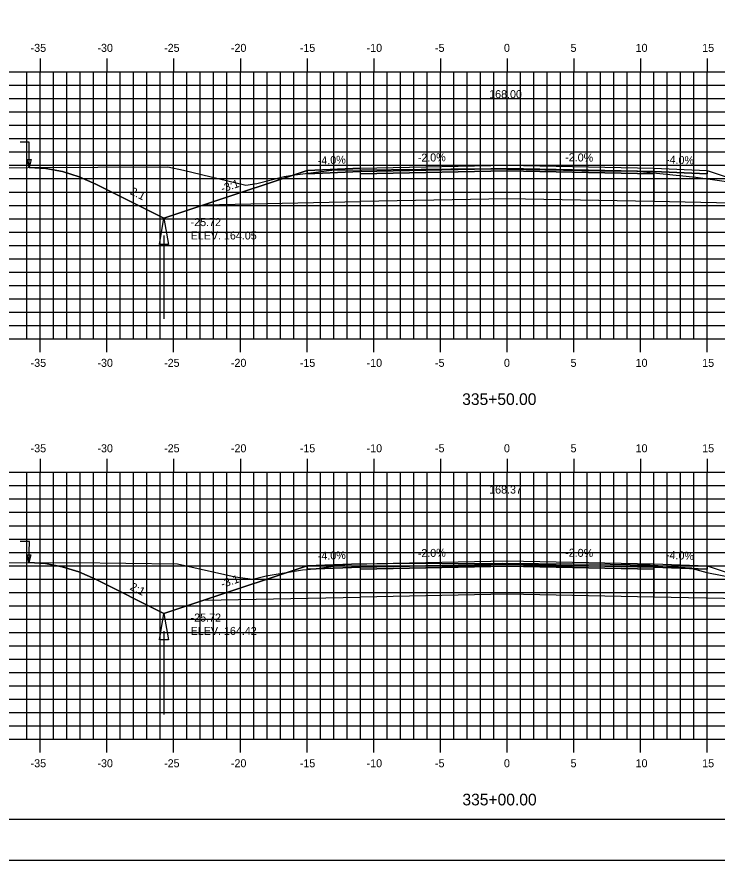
# Model space of a CAD drawing. Extents: x 1142089 to 1142259, y 608981 to 609091.
# Drawn here: x 1142135.8 to 1142188.3, y 608981.3 to 609044.5 of the extents above; entities that cross this region are included whole.
import ezdxf

# ---------------------------------------------------------------- set-up
doc = ezdxf.new("R2010")
doc.units = 0
for name, color, linetype in [('ANNOTATION', 7, 'Continuous'), ('BORDER', 7, 'Continuous'), ('D_Drainage_Ditch_Line', 7, 'Continuous'), ('D_Roadway_Centerline', 7, 'Continuous'), ('D_Roadway_Centerline_Text', 7, 'Continuous'), ('D_Roadway_Edge_Shoulder', 7, 'Continuous'), ('D_Roadway_Edge_TW', 7, 'Continuous'), ('D_Roadway_Pavement', 7, 'Continuous'), ('D_Roadway_SlopeLines', 7, 'Continuous'), ('D_Roadway_SubGrade', 7, 'Continuous'), ('D_Text_Standard', 7, 'Continuous'), ('H_V ANNOTATION', 7, 'Continuous'), ('MAJOR', 7, 'Continuous'), ('MINOR', 7, 'Continuous'), ('PLOT BOUNDARY', 7, 'Continuous'), ('S_Roadway_Centerline', 7, 'Continuous')]:
    doc.layers.add(name, color=color, linetype=linetype)

msp = doc.modelspace()

# ---------------------------------------------------------------- linework, layer by layer
for points in [[(1142136.708, 609033.172), (1142137.958, 609033.099), (1142139.208, 609032.868), (1142140.458, 609032.48), (1142141.708, 609031.934), (1142146.816, 609029.38), (1142149.816, 609030.38), (1142157.539, 609032.955), (1142157.54, 609032.955), (1142161.54, 609033.115), (1142172.54, 609033.335), (1142183.54, 609033.115), (1142187.54, 609032.955), (1142195.264, 609030.38), (1142198.264, 609029.38), (1142201.423, 609030.96), (1142202.673, 609031.506), (1142203.923, 609031.896), (1142205.173, 609032.129), (1142206.423, 609032.206)], [(1142136.678, 609003.566), (1142137.928, 609003.49), (1142139.178, 609003.257), (1142140.428, 609002.867), (1142141.678, 609002.32), (1142146.816, 608999.752), (1142149.816, 609000.752), (1142157.539, 609003.326), (1142157.54, 609003.326), (1142161.54, 609003.486), (1142172.54, 609003.706), (1142183.54, 609003.486), (1142187.54, 609003.326), (1142195.264, 609000.752), (1142198.264, 608999.752), (1142201.207, 609001.223), (1142202.457, 609001.767), (1142203.707, 609002.15), (1142204.957, 609002.371), (1142206.207, 609002.43)]]:
    msp.add_lwpolyline(points)
at = {"layer": 'BORDER'}
msp.add_lwpolyline([(1142097.541, 608984.335), (1142257.541, 608984.335), (1142257.541, 609089.335), (1142097.541, 609089.335)], close=True, dxfattribs=at)
at = {"layer": 'D_Drainage_Ditch_Line'}
for p, q in [((1142146.816, 609028.068), (1142146.815, 609021.824)), ((1142146.816, 608998.439), (1142146.815, 608992.196))]:
    msp.add_line(p, q, dxfattribs=at)
for points in [[(1142147.144, 609027.412), (1142146.488, 609027.412), (1142146.816, 609029.38)], [(1142147.144, 608997.783), (1142146.488, 608997.783), (1142146.816, 608999.752)]]:
    msp.add_lwpolyline(points, close=True, dxfattribs=at)
at = {"layer": 'D_Roadway_Edge_Shoulder'}
for points in [[(1142161.54, 609033.115), (1142157.54, 609032.955), (1142157.54, 609032.705), (1142161.54, 609032.865)], [(1142183.54, 609033.115), (1142187.54, 609032.955), (1142187.54, 609032.705), (1142183.54, 609032.865)], [(1142161.54, 609003.486), (1142157.54, 609003.326), (1142157.54, 609003.076), (1142161.54, 609003.236)], [(1142183.54, 609003.486), (1142187.54, 609003.326), (1142187.54, 609003.076), (1142183.54, 609003.236)]]:
    msp.add_lwpolyline(points, close=True, dxfattribs=at)
at = {"layer": 'D_Roadway_Edge_TW'}
for points in [[(1142161.54, 609032.865), (1142161.54, 609033.115), (1142172.54, 609033.335), (1142183.54, 609033.115), (1142183.54, 609032.865), (1142172.54, 609033.085)], [(1142161.54, 609003.236), (1142161.54, 609003.486), (1142172.54, 609003.706), (1142183.54, 609003.486), (1142183.54, 609003.236), (1142172.54, 609003.456)]]:
    msp.add_lwpolyline(points, close=True, dxfattribs=at)
at = {"layer": 'D_Roadway_Pavement'}
for points in [[(1142161.54, 609032.698), (1142161.54, 609032.865), (1142172.54, 609033.085), (1142183.54, 609032.865), (1142183.54, 609032.698), (1142172.54, 609032.918)], [(1142161.54, 609003.069), (1142161.54, 609003.236), (1142172.54, 609003.456), (1142183.54, 609003.236), (1142183.54, 609003.069), (1142172.54, 609003.289)]]:
    msp.add_lwpolyline(points, close=True, dxfattribs=at)
at = {"layer": 'D_Roadway_SlopeLines'}
for points in [[(1142146.816, 609029.38), (1142141.708, 609031.934), (1142140.458, 609032.48), (1142139.208, 609032.868), (1142137.958, 609033.099), (1142136.708, 609033.172)], [(1142149.816, 609030.38), (1142146.816, 609029.38)], [(1142146.816, 608999.752), (1142141.678, 609002.32), (1142140.428, 609002.867), (1142139.178, 609003.257), (1142137.928, 609003.49), (1142136.678, 609003.566)], [(1142149.816, 609000.752), (1142146.816, 608999.752)]]:
    msp.add_lwpolyline(points, dxfattribs=at)
at = {"layer": 'D_Roadway_SubGrade'}
for points in [[(1142161.54, 609032.698), (1142161.54, 609032.865), (1142157.54, 609032.705), (1142157.54, 609032.955), (1142157.539, 609032.955), (1142149.816, 609030.38), (1142161.54, 609030.615)], [(1142161.54, 609030.615), (1142161.54, 609032.698), (1142172.54, 609032.918), (1142183.54, 609032.698), (1142183.54, 609030.615), (1142172.54, 609030.835)], [(1142183.54, 609032.698), (1142183.54, 609032.865), (1142187.54, 609032.705), (1142187.54, 609032.955), (1142187.54, 609032.955), (1142195.264, 609030.38), (1142183.54, 609030.615)], [(1142161.54, 609003.069), (1142161.54, 609003.236), (1142157.54, 609003.076), (1142157.54, 609003.326), (1142157.539, 609003.326), (1142149.816, 609000.752), (1142161.54, 609000.986)], [(1142161.54, 609000.986), (1142161.54, 609003.069), (1142172.54, 609003.289), (1142183.54, 609003.069), (1142183.54, 609000.986), (1142172.54, 609001.206)], [(1142183.54, 609003.069), (1142183.54, 609003.236), (1142187.54, 609003.076), (1142187.54, 609003.326), (1142187.54, 609003.326), (1142195.264, 609000.752), (1142183.54, 609000.986)]]:
    msp.add_lwpolyline(points, close=True, dxfattribs=at)
at = {"layer": 'D_Text_Standard'}
for points in [[(1142136.708, 609033.184), (1142136.718, 609035.076), (1142136.038, 609035.076)], [(1142136.678, 609003.57), (1142136.725, 609005.14), (1142136.045, 609005.14)]]:
    msp.add_lwpolyline(points, dxfattribs=at)
for points in [[(1142136.708, 609033.184), (1142136.566, 609033.767), (1142136.857, 609033.765)], [(1142136.678, 609003.57), (1142136.55, 609004.157), (1142136.841, 609004.148)]]:
    msp.add_lwpolyline(points, close=True, dxfattribs=at)
at = {"layer": 'MAJOR'}
for p, q in [((1142137.54, 609041.337), (1142137.54, 609040.335)), ((1142142.54, 609041.337), (1142142.54, 609040.335)), ((1142147.54, 609041.337), (1142147.54, 609040.335)), ((1142152.54, 609041.337), (1142152.54, 609040.335)), ((1142157.54, 609041.337), (1142157.54, 609040.335)), ((1142162.54, 609041.337), (1142162.54, 609040.335)), ((1142167.54, 609041.337), (1142167.54, 609040.335)), ((1142172.54, 609041.337), (1142172.54, 609040.335)), ((1142177.54, 609041.337), (1142177.54, 609040.335)), ((1142182.54, 609041.337), (1142182.54, 609040.335)), ((1142187.54, 609041.337), (1142187.54, 609040.335)), ((1142102.54, 609040.335), (1142242.54, 609040.335)), ((1142102.54, 609040.335), (1142242.54, 609040.335)), ((1142137.54, 609020.335), (1142137.54, 609040.335)), ((1142142.54, 609020.335), (1142142.54, 609040.335)), ((1142147.54, 609020.335), (1142147.54, 609040.335)), ((1142152.54, 609020.335), (1142152.54, 609040.335)), ((1142157.54, 609020.335), (1142157.54, 609040.335)), ((1142162.54, 609020.335), (1142162.54, 609040.335)), ((1142167.54, 609020.335), (1142167.54, 609040.335)), ((1142172.54, 609020.335), (1142172.54, 609040.335)), ((1142177.54, 609020.335), (1142177.54, 609040.335)), ((1142182.54, 609020.335), (1142182.54, 609040.335)), ((1142187.54, 609020.335), (1142187.54, 609040.335)), ((1142102.54, 609035.335), (1142242.54, 609035.335)), ((1142102.54, 609030.335), (1142242.54, 609030.335)), ((1142102.54, 609025.335), (1142242.54, 609025.335)), ((1142102.54, 609020.335), (1142242.54, 609020.335)), ((1142102.54, 609020.335), (1142242.54, 609020.335)), ((1142137.54, 609019.333), (1142137.54, 609020.335)), ((1142142.54, 609019.333), (1142142.54, 609020.335)), ((1142147.54, 609019.333), (1142147.54, 609020.335)), ((1142152.54, 609019.333), (1142152.54, 609020.335)), ((1142157.54, 609019.333), (1142157.54, 609020.335)), ((1142162.54, 609019.333), (1142162.54, 609020.335)), ((1142167.54, 609019.333), (1142167.54, 609020.335)), ((1142172.54, 609019.333), (1142172.54, 609020.335)), ((1142177.54, 609019.333), (1142177.54, 609020.335)), ((1142182.54, 609019.333), (1142182.54, 609020.335)), ((1142187.54, 609019.333), (1142187.54, 609020.335)), ((1142137.54, 609011.337), (1142137.54, 609010.335)), ((1142142.54, 609011.337), (1142142.54, 609010.335)), ((1142147.54, 609011.337), (1142147.54, 609010.335)), ((1142152.54, 609011.337), (1142152.54, 609010.335)), ((1142157.54, 609011.337), (1142157.54, 609010.335)), ((1142162.54, 609011.337), (1142162.54, 609010.335)), ((1142167.54, 609011.337), (1142167.54, 609010.335)), ((1142172.54, 609011.337), (1142172.54, 609010.335)), ((1142177.54, 609011.337), (1142177.54, 609010.335)), ((1142182.54, 609011.337), (1142182.54, 609010.335)), ((1142187.54, 609011.337), (1142187.54, 609010.335)), ((1142102.54, 609010.335), (1142242.54, 609010.335)), ((1142102.54, 609010.335), (1142242.54, 609010.335)), ((1142137.54, 608990.335), (1142137.54, 609010.335)), ((1142142.54, 608990.335), (1142142.54, 609010.335)), ((1142147.54, 608990.335), (1142147.54, 609010.335)), ((1142152.54, 608990.335), (1142152.54, 609010.335)), ((1142157.54, 608990.335), (1142157.54, 609010.335)), ((1142162.54, 608990.335), (1142162.54, 609010.335)), ((1142167.54, 608990.335), (1142167.54, 609010.335)), ((1142172.54, 608990.335), (1142172.54, 609010.335)), ((1142177.54, 608990.335), (1142177.54, 609010.335)), ((1142182.54, 608990.335), (1142182.54, 609010.335)), ((1142187.54, 608990.335), (1142187.54, 609010.335)), ((1142102.54, 609005.335), (1142242.54, 609005.335)), ((1142102.54, 609000.335), (1142242.54, 609000.335)), ((1142102.54, 608995.335), (1142242.54, 608995.335)), ((1142102.54, 608990.335), (1142242.54, 608990.335)), ((1142102.54, 608990.335), (1142242.54, 608990.335)), ((1142137.54, 608989.333), (1142137.54, 608990.335)), ((1142142.54, 608989.333), (1142142.54, 608990.335)), ((1142147.54, 608989.333), (1142147.54, 608990.335)), ((1142152.54, 608989.333), (1142152.54, 608990.335)), ((1142157.54, 608989.333), (1142157.54, 608990.335)), ((1142162.54, 608989.333), (1142162.54, 608990.335)), ((1142167.54, 608989.333), (1142167.54, 608990.335)), ((1142172.54, 608989.333), (1142172.54, 608990.335)), ((1142177.54, 608989.333), (1142177.54, 608990.335)), ((1142182.54, 608989.333), (1142182.54, 608990.335)), ((1142187.54, 608989.333), (1142187.54, 608990.335))]:
    msp.add_line(p, q, dxfattribs=at)
at = {"layer": 'MINOR'}
for p, q in [((1142136.54, 609020.335), (1142136.54, 609040.335)), ((1142138.54, 609020.335), (1142138.54, 609040.335)), ((1142139.54, 609020.335), (1142139.54, 609040.335)), ((1142140.54, 609020.335), (1142140.54, 609040.335)), ((1142141.54, 609020.335), (1142141.54, 609040.335)), ((1142143.54, 609020.335), (1142143.54, 609040.335)), ((1142144.54, 609020.335), (1142144.54, 609040.335)), ((1142145.54, 609020.335), (1142145.54, 609040.335)), ((1142146.54, 609020.335), (1142146.54, 609040.335)), ((1142148.54, 609020.335), (1142148.54, 609040.335)), ((1142149.54, 609020.335), (1142149.54, 609040.335)), ((1142150.54, 609020.335), (1142150.54, 609040.335)), ((1142151.54, 609020.335), (1142151.54, 609040.335)), ((1142153.54, 609020.335), (1142153.54, 609040.335)), ((1142154.54, 609020.335), (1142154.54, 609040.335)), ((1142155.54, 609020.335), (1142155.54, 609040.335)), ((1142156.54, 609020.335), (1142156.54, 609040.335)), ((1142158.54, 609020.335), (1142158.54, 609040.335)), ((1142159.54, 609020.335), (1142159.54, 609040.335)), ((1142160.54, 609020.335), (1142160.54, 609040.335)), ((1142161.54, 609020.335), (1142161.54, 609040.335)), ((1142163.54, 609020.335), (1142163.54, 609040.335)), ((1142164.54, 609020.335), (1142164.54, 609040.335)), ((1142165.54, 609020.335), (1142165.54, 609040.335)), ((1142166.54, 609020.335), (1142166.54, 609040.335)), ((1142168.54, 609020.335), (1142168.54, 609040.335)), ((1142169.54, 609020.335), (1142169.54, 609040.335)), ((1142170.54, 609020.335), (1142170.54, 609040.335)), ((1142171.54, 609020.335), (1142171.54, 609040.335)), ((1142173.54, 609020.335), (1142173.54, 609040.335)), ((1142174.54, 609020.335), (1142174.54, 609040.335)), ((1142175.54, 609020.335), (1142175.54, 609040.335)), ((1142176.54, 609020.335), (1142176.54, 609040.335)), ((1142178.54, 609020.335), (1142178.54, 609040.335)), ((1142179.54, 609020.335), (1142179.54, 609040.335)), ((1142180.54, 609020.335), (1142180.54, 609040.335)), ((1142181.54, 609020.335), (1142181.54, 609040.335)), ((1142183.54, 609020.335), (1142183.54, 609040.335)), ((1142184.54, 609020.335), (1142184.54, 609040.335)), ((1142185.54, 609020.335), (1142185.54, 609040.335)), ((1142186.54, 609020.335), (1142186.54, 609040.335)), ((1142102.54, 609039.335), (1142242.54, 609039.335)), ((1142102.54, 609038.335), (1142242.54, 609038.335)), ((1142102.54, 609037.335), (1142242.54, 609037.335)), ((1142102.54, 609036.335), (1142242.54, 609036.335)), ((1142102.54, 609034.335), (1142242.54, 609034.335)), ((1142102.54, 609033.335), (1142242.54, 609033.335)), ((1142102.54, 609032.335), (1142242.54, 609032.335)), ((1142102.54, 609031.335), (1142242.54, 609031.335)), ((1142102.54, 609029.335), (1142242.54, 609029.335)), ((1142102.54, 609028.335), (1142242.54, 609028.335)), ((1142102.54, 609027.335), (1142242.54, 609027.335)), ((1142102.54, 609026.335), (1142242.54, 609026.335)), ((1142102.54, 609024.335), (1142242.54, 609024.335)), ((1142102.54, 609023.335), (1142242.54, 609023.335)), ((1142102.54, 609022.335), (1142242.54, 609022.335)), ((1142102.54, 609021.335), (1142242.54, 609021.335)), ((1142136.54, 608990.335), (1142136.54, 609010.335)), ((1142138.54, 608990.335), (1142138.54, 609010.335)), ((1142139.54, 608990.335), (1142139.54, 609010.335)), ((1142140.54, 608990.335), (1142140.54, 609010.335)), ((1142141.54, 608990.335), (1142141.54, 609010.335)), ((1142143.54, 608990.335), (1142143.54, 609010.335)), ((1142144.54, 608990.335), (1142144.54, 609010.335)), ((1142145.54, 608990.335), (1142145.54, 609010.335)), ((1142146.54, 608990.335), (1142146.54, 609010.335)), ((1142148.54, 608990.335), (1142148.54, 609010.335)), ((1142149.54, 608990.335), (1142149.54, 609010.335)), ((1142150.54, 608990.335), (1142150.54, 609010.335)), ((1142151.54, 608990.335), (1142151.54, 609010.335)), ((1142153.54, 608990.335), (1142153.54, 609010.335)), ((1142154.54, 608990.335), (1142154.54, 609010.335)), ((1142155.54, 608990.335), (1142155.54, 609010.335)), ((1142156.54, 608990.335), (1142156.54, 609010.335)), ((1142158.54, 608990.335), (1142158.54, 609010.335)), ((1142159.54, 608990.335), (1142159.54, 609010.335)), ((1142160.54, 608990.335), (1142160.54, 609010.335)), ((1142161.54, 608990.335), (1142161.54, 609010.335)), ((1142163.54, 608990.335), (1142163.54, 609010.335)), ((1142164.54, 608990.335), (1142164.54, 609010.335)), ((1142165.54, 608990.335), (1142165.54, 609010.335)), ((1142166.54, 608990.335), (1142166.54, 609010.335)), ((1142168.54, 608990.335), (1142168.54, 609010.335)), ((1142169.54, 608990.335), (1142169.54, 609010.335)), ((1142170.54, 608990.335), (1142170.54, 609010.335)), ((1142171.54, 608990.335), (1142171.54, 609010.335)), ((1142173.54, 608990.335), (1142173.54, 609010.335)), ((1142174.54, 608990.335), (1142174.54, 609010.335)), ((1142175.54, 608990.335), (1142175.54, 609010.335)), ((1142176.54, 608990.335), (1142176.54, 609010.335)), ((1142178.54, 608990.335), (1142178.54, 609010.335)), ((1142179.54, 608990.335), (1142179.54, 609010.335)), ((1142180.54, 608990.335), (1142180.54, 609010.335)), ((1142181.54, 608990.335), (1142181.54, 609010.335)), ((1142183.54, 608990.335), (1142183.54, 609010.335)), ((1142184.54, 608990.335), (1142184.54, 609010.335)), ((1142185.54, 608990.335), (1142185.54, 609010.335)), ((1142186.54, 608990.335), (1142186.54, 609010.335)), ((1142102.54, 609009.335), (1142242.54, 609009.335)), ((1142102.54, 609008.335), (1142242.54, 609008.335)), ((1142102.54, 609007.335), (1142242.54, 609007.335)), ((1142102.54, 609006.335), (1142242.54, 609006.335)), ((1142102.54, 609004.335), (1142242.54, 609004.335)), ((1142102.54, 609003.335), (1142242.54, 609003.335)), ((1142102.54, 609002.335), (1142242.54, 609002.335)), ((1142102.54, 609001.335), (1142242.54, 609001.335)), ((1142102.54, 608999.335), (1142242.54, 608999.335)), ((1142102.54, 608998.335), (1142242.54, 608998.335)), ((1142102.54, 608997.335), (1142242.54, 608997.335)), ((1142102.54, 608996.335), (1142242.54, 608996.335)), ((1142102.54, 608994.335), (1142242.54, 608994.335)), ((1142102.54, 608993.335), (1142242.54, 608993.335)), ((1142102.54, 608992.335), (1142242.54, 608992.335)), ((1142102.54, 608991.335), (1142242.54, 608991.335))]:
    msp.add_line(p, q, dxfattribs=at)
at = {"layer": 'PLOT BOUNDARY'}
msp.add_lwpolyline([(1142089.447, 608981.276), (1142259.447, 608981.276), (1142259.447, 609091.276), (1142089.447, 609091.276)], close=True, dxfattribs=at)
at = {"layer": 'S_Roadway_Centerline'}
for points in [[(1142121.671, 609033.112), (1142126.127, 609033.122), (1142147.112, 609033.221), (1142148.27, 609032.961), (1142152.957, 609031.847), (1142153.787, 609031.981), (1142155.823, 609032.494), (1142156.613, 609032.611), (1142159.401, 609032.97), (1142168.323, 609033.066), (1142171.191, 609033.079), (1142179.536, 609032.919), (1142182.26, 609032.89), (1142183, 609032.834), (1142186.686, 609032.455), (1142188.804, 609032.159), (1142190.283, 609031.867), (1142191.191, 609032.024), (1142195.319, 609032.212), (1142205.426, 609032.209), (1142222.534, 609032.153)], [(1142120.248, 609003.54), (1142140.088, 609003.572), (1142147.837, 609003.464), (1142152.153, 609002.5), (1142153.465, 609002.339), (1142154.47, 609002.585), (1142157.194, 609003.025), (1142158.087, 609003.093), (1142160.552, 609003.459), (1142163.514, 609003.498), (1142172.183, 609003.534), (1142180.268, 609003.447), (1142183.249, 609003.394), (1142185.379, 609003.23), (1142186.373, 609003.17), (1142186.402, 609003.118), (1142187.497, 609002.831), (1142191.74, 609001.996), (1142192.511, 609002.174), (1142195.062, 609002.623), (1142212.721, 609002.317), (1142224.423, 609002.225)]]:
    msp.add_lwpolyline(points, dxfattribs=at)

# ---------------------------------------------------------------- texts
at = {"layer": 'ANNOTATION'}
for s, rotation, p in [('-4.0%', 2.29061, (1142158.356, 609033.388)), ('-2.0%', 1.14576, (1142165.843, 609033.601)), ('-2.0%', 358.85424, (1142176.883, 609033.648)), ('-4.0%', 357.70939, (1142184.436, 609033.48)), ('-3:1', 18.43482, (1142151.195, 609031.294)), ('2:1', 333.43495, (1142144.229, 609031.192)), ('-4.0%', 2.29061, (1142158.356, 609003.76)), ('-2.0%', 1.14576, (1142165.843, 609003.972)), ('-2.0%', 358.85424, (1142176.883, 609004.019)), ('-4.0%', 357.70939, (1142184.436, 609003.851)), ('-3:1', 18.43482, (1142151.195, 609001.665)), ('2:1', 333.43495, (1142144.214, 609001.571))]:
    msp.add_text(s, height=0.6, rotation=rotation, dxfattribs=at).set_placement(p)
at = {"layer": 'D_Roadway_Centerline'}
for s, p in [('C', (1142172.535, 609033.335)), ('L', (1142172.54, 609033.327)), ('C', (1142172.535, 609003.706)), ('L', (1142172.54, 609003.699))]:
    msp.add_text(s, height=0.0146, dxfattribs=at).set_placement(p)
at = {"layer": 'D_Roadway_Centerline_Text'}
for s, p in [('168.00', (1142171.192, 609038.367)), ('168.37', (1142171.192, 609008.738))]:
    msp.add_text(s, height=0.6, dxfattribs=at).set_placement(p)
at = {"layer": 'D_Text_Standard'}
for s, p in [('-25.72', (1142148.816, 609028.78)), ('ELEV. 164.05', (1142148.816, 609027.778)), ('-25.72', (1142148.816, 608999.152)), ('ELEV. 164.42', (1142148.816, 608998.15))]:
    msp.add_text(s, height=0.6, dxfattribs=at).set_placement(p)
at = {"layer": 'H_V ANNOTATION'}
for s, height, p in [('-35', 0.6, (1142136.821, 609041.835)), ('-30', 0.6, (1142141.829, 609041.835)), ('-25', 0.6, (1142146.826, 609041.835)), ('-20', 0.6, (1142151.834, 609041.835)), ('-15', 0.6, (1142156.997, 609041.835)), ('-10', 0.6, (1142162.005, 609041.835)), ('-5', 0.6, (1142167.131, 609041.835)), ('0', 0.6, (1142172.299, 609041.835)), ('5', 0.6, (1142177.291, 609041.835)), ('10', 0.6, (1142182.166, 609041.835)), ('15', 0.6, (1142187.158, 609041.835)), ('-35', 0.6, (1142136.821, 609018.235)), ('-30', 0.6, (1142141.829, 609018.235)), ('-25', 0.6, (1142146.826, 609018.235)), ('-20', 0.6, (1142151.834, 609018.235)), ('-15', 0.6, (1142156.997, 609018.235)), ('-10', 0.6, (1142162.005, 609018.235)), ('-5', 0.6, (1142167.131, 609018.235)), ('0', 0.6, (1142172.299, 609018.235)), ('5', 0.6, (1142177.291, 609018.235)), ('10', 0.6, (1142182.166, 609018.235)), ('15', 0.6, (1142187.158, 609018.235)), ('335+50.00', 0.875, (1142169.169, 609015.378)), ('-35', 0.6, (1142136.821, 609011.835)), ('-30', 0.6, (1142141.829, 609011.835)), ('-25', 0.6, (1142146.826, 609011.835)), ('-20', 0.6, (1142151.834, 609011.835)), ('-15', 0.6, (1142156.997, 609011.835)), ('-10', 0.6, (1142162.005, 609011.835)), ('-5', 0.6, (1142167.131, 609011.835)), ('0', 0.6, (1142172.299, 609011.835)), ('5', 0.6, (1142177.291, 609011.835)), ('10', 0.6, (1142182.166, 609011.835)), ('15', 0.6, (1142187.158, 609011.835)), ('-35', 0.6, (1142136.821, 608988.235)), ('-30', 0.6, (1142141.829, 608988.235)), ('-25', 0.6, (1142146.826, 608988.235)), ('-20', 0.6, (1142151.834, 608988.235)), ('-15', 0.6, (1142156.997, 608988.235)), ('-10', 0.6, (1142162.005, 608988.235)), ('-5', 0.6, (1142167.131, 608988.235)), ('0', 0.6, (1142172.299, 608988.235)), ('5', 0.6, (1142177.291, 608988.235)), ('10', 0.6, (1142182.166, 608988.235)), ('15', 0.6, (1142187.158, 608988.235)), ('335+00.00', 0.875, (1142169.185, 608985.378))]:
    msp.add_text(s, height=height, dxfattribs=at).set_placement(p)
at = {"layer": 'S_Roadway_Centerline'}
for s, p in [('L', (1142171.182, 609033.071)), ('C', (1142171.186, 609033.079)), ('L', (1142172.174, 609003.527)), ('C', (1142172.178, 609003.534))]:
    msp.add_text(s, height=0.0146, dxfattribs=at).set_placement(p)

doc.saveas('drawing.dxf')
